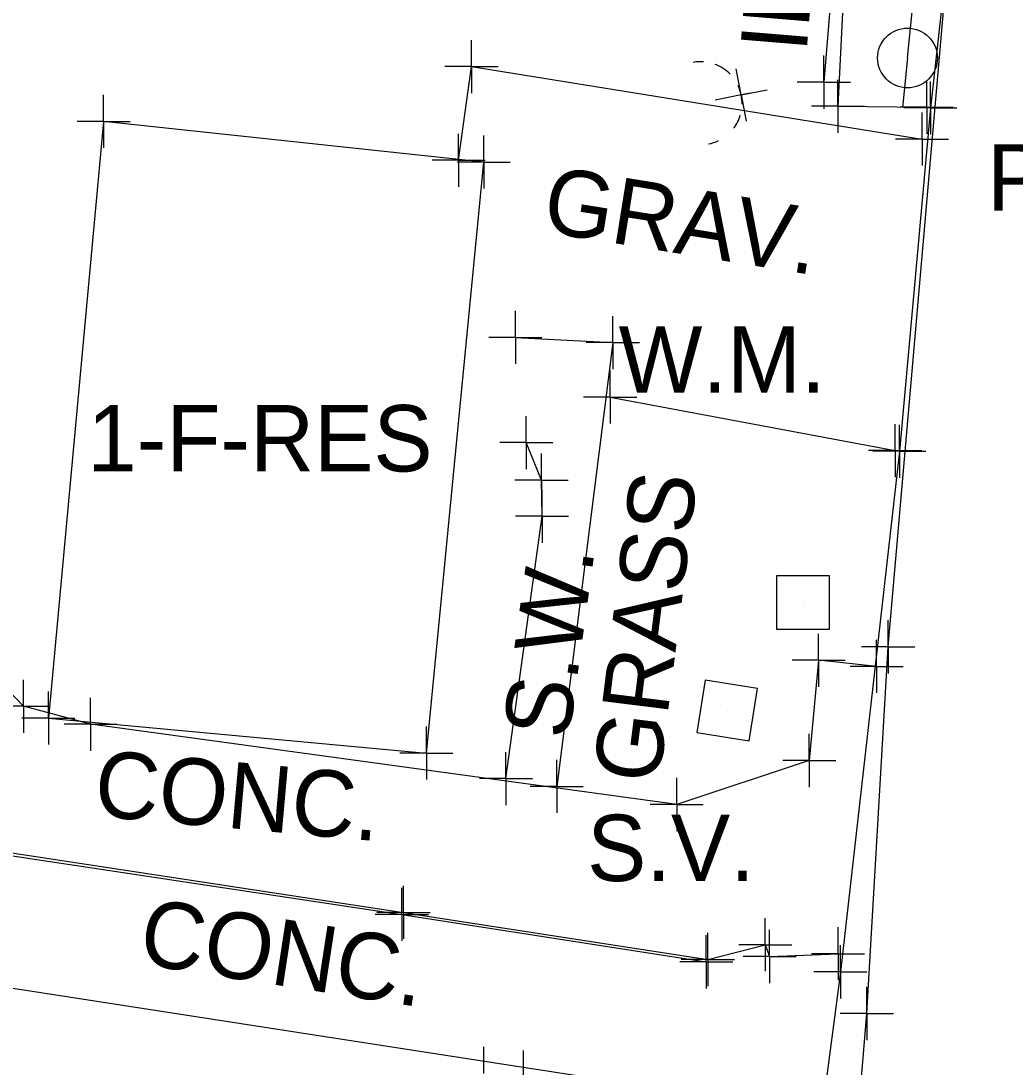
# Model space of a CAD drawing. Extents: x 0 to 1944463, y 0 to 420651.
# Drawn here: x 1943325.3 to 1943400.2, y 417489.4 to 417568.2 of the extents above; entities that cross this region are included whole.
import ezdxf

# ---------------------------------------------------------------- set-up
doc = ezdxf.new("R2010")
doc.units = 0
for name, color, linetype in [('SUR - NON-TRAN - Buildings', 7, 'Continuous'), ('SUR - NON-TRAN - Buildings - Points - Locators', 7, 'Continuous'), ('SUR - NON-TRAN - Buildings Text', 7, 'Continuous'), ('SUR - NON-TRAN - Features', 7, 'Continuous'), ('SUR - NON-TRAN - Features - Points - Locators', 7, 'Continuous'), ('SUR - NON-TRAN - Features Text', 7, 'Continuous'), ('SUR - PROPERTY - Property Lines', 7, 'Continuous'), ('SUR - TRAN - Features', 7, 'Continuous'), ('SUR - TRAN - Features - Points - Locators', 7, 'Continuous'), ('SUR - TRAN - Features Text', 7, 'Continuous'), ('SUR - TRAN - Roads', 7, 'Continuous'), ('SUR - UTL - Gas', 7, 'Continuous'), ('SUR - UTL - Gas - Points - Locators', 7, 'Continuous'), ('SUR - UTL - Poles and Miscellaneous', 7, 'Continuous'), ('SUR - UTL - Poles and Miscellaneous - Points - Locators', 7, 'Continuous'), ('SUR - UTL - Poles and Miscellaneous Text', 7, 'Continuous'), ('SUR - UTL - Sanitary Sewer', 7, 'Continuous'), ('SUR - UTL - Sanitary Sewer Text', 7, 'Continuous'), ('SUR - UTL - Water', 7, 'Continuous'), ('SUR - UTL - Water Text', 7, 'Continuous'), ('SUR - VEG - Features Text', 7, 'Continuous')]:
    doc.layers.add(name, color=color, linetype=linetype)

msp = doc.modelspace()

# ---------------------------------------------------------------- linework, layer by layer
at = {"layer": 'SUR - NON-TRAN - Buildings'}
msp.add_lwpolyline([(1943360.144, 417557.575), (1943331.513, 417560.638), (1943327.352, 417515.696), (1943355.823, 417513.052)], close=True, dxfattribs=at)
at = {"layer": 'SUR - NON-TRAN - Buildings - Points - Locators'}
for p, q in [((1943331.513, 417560.638), (1943331.513, 417562.638)), ((1943331.513, 417560.638), (1943329.513, 417560.638)), ((1943331.513, 417560.638), (1943333.513, 417560.638)), ((1943331.513, 417560.638), (1943331.513, 417558.638)), ((1943360.144, 417557.575), (1943360.144, 417559.575)), ((1943360.144, 417557.575), (1943358.144, 417557.575)), ((1943360.144, 417557.575), (1943362.144, 417557.575)), ((1943360.144, 417557.575), (1943360.144, 417555.575)), ((1943327.352, 417515.696), (1943327.352, 417517.696)), ((1943327.352, 417515.696), (1943325.352, 417515.696)), ((1943327.352, 417515.696), (1943329.352, 417515.696)), ((1943327.352, 417515.696), (1943327.352, 417513.696)), ((1943355.823, 417513.052), (1943355.823, 417515.052)), ((1943355.823, 417513.052), (1943353.823, 417513.052)), ((1943355.823, 417513.052), (1943357.823, 417513.052)), ((1943355.823, 417513.052), (1943355.823, 417511.052))]:
    msp.add_line(p, q, dxfattribs=at)
at = {"layer": 'SUR - NON-TRAN - Features'}
for points in [[(1943388.617, 417598.372), (1943385.759, 417563.595)], [(1943362.527, 417544.367), (1943369.865, 417543.98), (1943365.641, 417510.541)], [(1943361.811, 417511.128), (1943364.535, 417530.891), (1943364.494, 417533.613), (1943363.347, 417536.444)]]:
    msp.add_lwpolyline(points, dxfattribs=at)
at = {"layer": 'SUR - NON-TRAN - Features - Points - Locators'}
for p, q in [((1943385.759, 417563.595), (1943385.759, 417565.595)), ((1943385.759, 417563.595), (1943383.759, 417563.595)), ((1943385.759, 417563.595), (1943387.759, 417563.595)), ((1943385.759, 417563.595), (1943385.759, 417561.595)), ((1943362.527, 417544.367), (1943362.527, 417546.367)), ((1943369.865, 417543.98), (1943369.865, 417545.98)), ((1943362.527, 417544.367), (1943360.527, 417544.367)), ((1943362.527, 417544.367), (1943364.527, 417544.367)), ((1943362.527, 417544.367), (1943362.527, 417542.367)), ((1943369.865, 417543.98), (1943367.865, 417543.98)), ((1943369.865, 417543.98), (1943371.865, 417543.98)), ((1943369.865, 417543.98), (1943369.865, 417541.98)), ((1943363.347, 417536.444), (1943363.347, 417538.444)), ((1943363.347, 417536.444), (1943361.347, 417536.444)), ((1943363.347, 417536.444), (1943365.347, 417536.444)), ((1943363.347, 417536.444), (1943363.347, 417534.444)), ((1943364.494, 417533.613), (1943364.494, 417535.613)), ((1943364.494, 417533.613), (1943362.494, 417533.613)), ((1943364.494, 417533.613), (1943366.494, 417533.613)), ((1943364.494, 417533.613), (1943364.494, 417531.613)), ((1943364.535, 417530.891), (1943364.535, 417532.891)), ((1943364.535, 417530.891), (1943362.535, 417530.891)), ((1943364.535, 417530.891), (1943366.535, 417530.891)), ((1943364.535, 417530.891), (1943364.535, 417528.891)), ((1943361.811, 417511.128), (1943361.811, 417513.128)), ((1943365.641, 417510.541), (1943365.641, 417512.541)), ((1943361.811, 417511.128), (1943359.811, 417511.128)), ((1943361.811, 417511.128), (1943363.811, 417511.128)), ((1943361.811, 417511.128), (1943361.811, 417509.128)), ((1943365.641, 417510.541), (1943363.641, 417510.541)), ((1943365.641, 417510.541), (1943367.641, 417510.541)), ((1943365.641, 417510.541), (1943365.641, 417508.541)), ((1943360.144, 417488.914), (1943360.144, 417490.914)), ((1943363.137, 417488.646), (1943363.137, 417490.646))]:
    msp.add_line(p, q, dxfattribs=at)
at = {"layer": 'SUR - PROPERTY - Property Lines'}
for p, q in [((1943393.78, 417561.652), (1943393.78, 417563.652)), ((1943393.78, 417561.652), (1943391.78, 417561.652)), ((1943393.78, 417561.652), (1943395.78, 417561.652)), ((1943393.78, 417561.652), (1943393.78, 417559.652)), ((1943391.448, 417535.786), (1943391.448, 417537.786)), ((1943391.448, 417535.786), (1943389.448, 417535.786)), ((1943391.448, 417535.786), (1943393.448, 417535.786)), ((1943391.448, 417535.786), (1943391.448, 417533.786)), ((1943387.006, 417496.574), (1943387.006, 417498.574)), ((1943387.006, 417496.574), (1943385.006, 417496.574)), ((1943387.006, 417496.574), (1943389.006, 417496.574)), ((1943387.006, 417496.574), (1943387.006, 417494.574))]:
    msp.add_line(p, q, dxfattribs=at)
at = {"layer": 'SUR - TRAN - Features'}
for points in [[(1943374.814, 417618.291), (1943390.429, 417618.211), (1943388.452, 417594.475), (1943386.82, 417561.779), (1943393.504, 417561.707)], [(1943358.252, 417557.708), (1943359.223, 417564.764), (1943393.159, 417559.31)], [(1943389.731, 417519.583), (1943385.369, 417520.046), (1943384.658, 417512.495), (1943374.674, 417509.182), (1943330.533, 417515.223), (1943325.469, 417516.576), (1943321.794, 417520.411), (1943319.08, 417525.649), (1943317.143, 417530.004), (1943315.757, 417536.1), (1943316.709, 417547.78), (1943301.671, 417548.773), (1943300.686, 417540.465), (1943280.895, 417542.23), (1943278.364, 417519.199), (1943302.138, 417516.619), (1943315.396, 417507.068), (1943316.483, 417506.757), (1943354.102, 417501.056), (1943377.023, 417497.5), (1943381.35, 417498.62), (1943381.676, 417497.726), (1943386.831, 417497.939)], [(1943369.664, 417539.877), (1943391.132, 417535.836)], [(1943289.19, 417511.615), (1943304.871, 417510.322), (1943315.963, 417506.608), (1943353.975, 417500.897), (1943376.9, 417497.329)], [(1943384.554, 417481.747), (1943375.941, 417487.388), (1943318.331, 417496.289), (1943305.868, 417491.574)]]:
    msp.add_lwpolyline(points, dxfattribs=at)
at = {"layer": 'SUR - TRAN - Features - Points - Locators'}
for p, q in [((1943359.223, 417564.764), (1943359.223, 417566.764)), ((1943359.223, 417564.764), (1943357.223, 417564.764)), ((1943359.223, 417564.764), (1943361.223, 417564.764)), ((1943359.223, 417564.764), (1943359.223, 417562.764)), ((1943386.82, 417561.779), (1943386.82, 417563.779)), ((1943393.504, 417561.707), (1943393.504, 417563.707)), ((1943386.82, 417561.779), (1943384.82, 417561.779)), ((1943386.82, 417561.779), (1943388.82, 417561.779)), ((1943386.82, 417561.779), (1943386.82, 417559.779)), ((1943393.504, 417561.707), (1943391.504, 417561.707)), ((1943393.504, 417561.707), (1943395.504, 417561.707)), ((1943393.504, 417561.707), (1943393.504, 417559.707)), ((1943393.159, 417559.31), (1943393.159, 417561.31)), ((1943358.252, 417557.708), (1943358.252, 417559.708)), ((1943393.159, 417559.31), (1943391.159, 417559.31)), ((1943393.159, 417559.31), (1943395.159, 417559.31)), ((1943393.159, 417559.31), (1943393.159, 417557.31)), ((1943358.252, 417557.708), (1943356.252, 417557.708)), ((1943358.252, 417557.708), (1943360.252, 417557.708)), ((1943358.252, 417557.708), (1943358.252, 417555.708)), ((1943369.664, 417539.877), (1943369.664, 417541.877)), ((1943369.664, 417539.877), (1943367.664, 417539.877)), ((1943369.664, 417539.877), (1943371.664, 417539.877)), ((1943369.664, 417539.877), (1943369.664, 417537.877)), ((1943391.132, 417535.836), (1943391.132, 417537.836)), ((1943391.132, 417535.836), (1943389.132, 417535.836)), ((1943391.132, 417535.836), (1943393.132, 417535.836)), ((1943391.132, 417535.836), (1943391.132, 417533.836)), ((1943385.369, 417520.046), (1943385.369, 417522.046)), ((1943389.731, 417519.583), (1943389.731, 417521.583)), ((1943385.369, 417520.046), (1943383.369, 417520.046)), ((1943385.369, 417520.046), (1943387.369, 417520.046)), ((1943385.369, 417520.046), (1943385.369, 417518.046)), ((1943389.731, 417519.583), (1943387.731, 417519.583)), ((1943389.731, 417519.583), (1943391.731, 417519.583)), ((1943389.731, 417519.583), (1943389.731, 417517.583)), ((1943325.469, 417516.576), (1943325.469, 417518.576)), ((1943325.469, 417516.576), (1943323.469, 417516.576)), ((1943325.469, 417516.576), (1943327.469, 417516.576)), ((1943325.469, 417516.576), (1943325.469, 417514.576)), ((1943330.533, 417515.223), (1943330.533, 417517.223)), ((1943330.533, 417515.223), (1943328.533, 417515.223)), ((1943330.533, 417515.223), (1943332.533, 417515.223)), ((1943330.533, 417515.223), (1943330.533, 417513.223)), ((1943384.658, 417512.495), (1943384.658, 417514.495)), ((1943384.658, 417512.495), (1943382.658, 417512.495)), ((1943384.658, 417512.495), (1943386.658, 417512.495)), ((1943384.658, 417512.495), (1943384.658, 417510.495)), ((1943374.674, 417509.182), (1943374.674, 417511.182)), ((1943374.674, 417509.182), (1943372.674, 417509.182)), ((1943374.674, 417509.182), (1943376.674, 417509.182)), ((1943374.674, 417509.182), (1943374.674, 417507.182)), ((1943353.975, 417500.897), (1943353.975, 417502.897)), ((1943354.102, 417501.056), (1943354.102, 417503.056)), ((1943353.975, 417500.897), (1943351.975, 417500.897)), ((1943354.102, 417501.056), (1943352.102, 417501.056)), ((1943353.975, 417500.897), (1943355.975, 417500.897)), ((1943353.975, 417500.897), (1943353.975, 417498.897)), ((1943354.102, 417501.056), (1943356.102, 417501.056)), ((1943354.102, 417501.056), (1943354.102, 417499.056)), ((1943381.35, 417498.62), (1943381.35, 417500.62)), ((1943376.9, 417497.329), (1943376.9, 417499.329)), ((1943377.023, 417497.5), (1943377.023, 417499.5)), ((1943381.676, 417497.726), (1943381.676, 417499.726)), ((1943386.831, 417497.939), (1943386.831, 417499.939)), ((1943381.35, 417498.62), (1943379.35, 417498.62)), ((1943381.35, 417498.62), (1943383.35, 417498.62)), ((1943381.35, 417498.62), (1943381.35, 417496.62)), ((1943381.676, 417497.726), (1943379.676, 417497.726)), ((1943381.676, 417497.726), (1943383.676, 417497.726)), ((1943381.676, 417497.726), (1943381.676, 417495.726)), ((1943386.831, 417497.939), (1943384.831, 417497.939)), ((1943386.831, 417497.939), (1943388.831, 417497.939)), ((1943386.831, 417497.939), (1943386.831, 417495.939)), ((1943376.9, 417497.329), (1943374.9, 417497.329)), ((1943377.023, 417497.5), (1943375.023, 417497.5)), ((1943376.9, 417497.329), (1943378.9, 417497.329)), ((1943376.9, 417497.329), (1943376.9, 417495.329)), ((1943377.023, 417497.5), (1943379.023, 417497.5)), ((1943377.023, 417497.5), (1943377.023, 417495.5))]:
    msp.add_line(p, q, dxfattribs=at)
at = {"layer": 'SUR - TRAN - Roads'}
msp.add_lwpolyline([(1943399.162, 417610.135), (1943393.78, 417561.652), (1943391.448, 417535.786), (1943387.006, 417496.574), (1943384.392, 417476.781), (1943383.862, 417459.391), (1943381.353, 417448.68)], dxfattribs=at)
at = {"layer": 'SUR - UTL - Gas'}
msp.add_lwpolyline([(1943380.613, 417418.365), (1943384.689, 417441.465), (1943388.995, 417493.436), (1943390.6, 417521.055), (1943395.849, 417581.366)], dxfattribs=at)
at = {"layer": 'SUR - UTL - Gas - Points - Locators'}
for p, q in [((1943390.6, 417521.055), (1943390.6, 417523.055)), ((1943390.6, 417521.055), (1943388.6, 417521.055)), ((1943390.6, 417521.055), (1943392.6, 417521.055)), ((1943390.6, 417521.055), (1943390.6, 417519.055)), ((1943388.995, 417493.436), (1943388.995, 417495.436)), ((1943388.995, 417493.436), (1943386.995, 417493.436)), ((1943388.995, 417493.436), (1943390.995, 417493.436)), ((1943388.995, 417493.436), (1943388.995, 417491.436))]:
    msp.add_line(p, q, dxfattribs=at)
at = {"layer": 'SUR - UTL - Poles and Miscellaneous'}
for p, q in [((1943392.059, 417565.42), (1943392.425, 417569.152)), ((1943392.059, 417565.42), (1943391.693, 417561.688)), ((1943380.224, 417562.766), (1943379.537, 417562.632))]:
    msp.add_line(p, q, dxfattribs=at)
msp.add_circle((1943392.059, 417565.42), 2.25, dxfattribs=at)
for start, end in [(86.19319, 100.08261), (44.5694, 69.33944), (358.52758, 25.0429), (322.88452, 343.22704), (281.00666, 295.62753)]:
    msp.add_arc((1943376.475, 417562.011), 3.125, start, end, dxfattribs=at)
at = {"layer": 'SUR - UTL - Poles and Miscellaneous - Points - Locators'}
for q in [(1943379.156, 417564.596), (1943377.574, 417562.25), (1943381.501, 417563.014), (1943379.919, 417560.669)]:
    msp.add_line((1943379.537, 417562.632), q, dxfattribs=at)
at = {"layer": 'SUR - UTL - Sanitary Sewer'}
msp.add_line((1943378.476, 417516.261), (1943378.476, 417516.261), dxfattribs=at)
msp.add_lwpolyline([(1943376.812, 417518.548), (1943376.19, 417514.597), (1943380.141, 417513.975), (1943380.763, 417517.926), (1943376.812, 417518.548)], dxfattribs=at)
at = {"layer": 'SUR - UTL - Water'}
msp.add_line((1943384.19, 417524.397), (1943384.19, 417524.397), dxfattribs=at)
msp.add_lwpolyline([(1943382.19, 417526.397), (1943382.19, 417522.397), (1943386.19, 417522.397), (1943386.19, 417526.397), (1943382.19, 417526.397)], dxfattribs=at)

# ---------------------------------------------------------------- texts
at = {"layer": 'SUR - NON-TRAN - Buildings Text'}
msp.add_text('1-F-RES', height=5, dxfattribs=at).set_placement((1943330.287, 417534.27))
at = {"layer": 'SUR - NON-TRAN - Features Text'}
for s, rotation, p in [('IRON', 85.30095, (1943384.452, 417565.777)), ('S.W.', 82.1497, (1943366.531, 417513.992))]:
    msp.add_text(s, height=5, rotation=rotation, dxfattribs=at).set_placement(p)
at = {"layer": 'SUR - TRAN - Features Text'}
for s, rotation, p in [('GRAV.', 350.86917, (1943364.416, 417552.358)), ('CONC.', 354.90486, (1943330.683, 417508.323)), ('CONC.', 351.21692, (1943334.02, 417497.202))]:
    msp.add_text(s, height=5, rotation=rotation, dxfattribs=at).set_placement(p)
at = {"layer": 'SUR - UTL - Poles and Miscellaneous Text'}
msp.add_text('PTC', height=5, dxfattribs=at).set_placement((1943398.059, 417553.92))
at = {"layer": 'SUR - UTL - Sanitary Sewer Text'}
msp.add_text('S.V.', height=5, dxfattribs=at).set_placement((1943367.927, 417503.411))
at = {"layer": 'SUR - UTL - Water Text'}
msp.add_text('W.M.', height=5, dxfattribs=at).set_placement((1943370.303, 417540.21))
at = {"layer": 'SUR - VEG - Features Text'}
msp.add_text('GRASS', height=5, rotation=82.87924, dxfattribs=at).set_placement((1943373.334, 417510.643))

doc.saveas('drawing.dxf')
